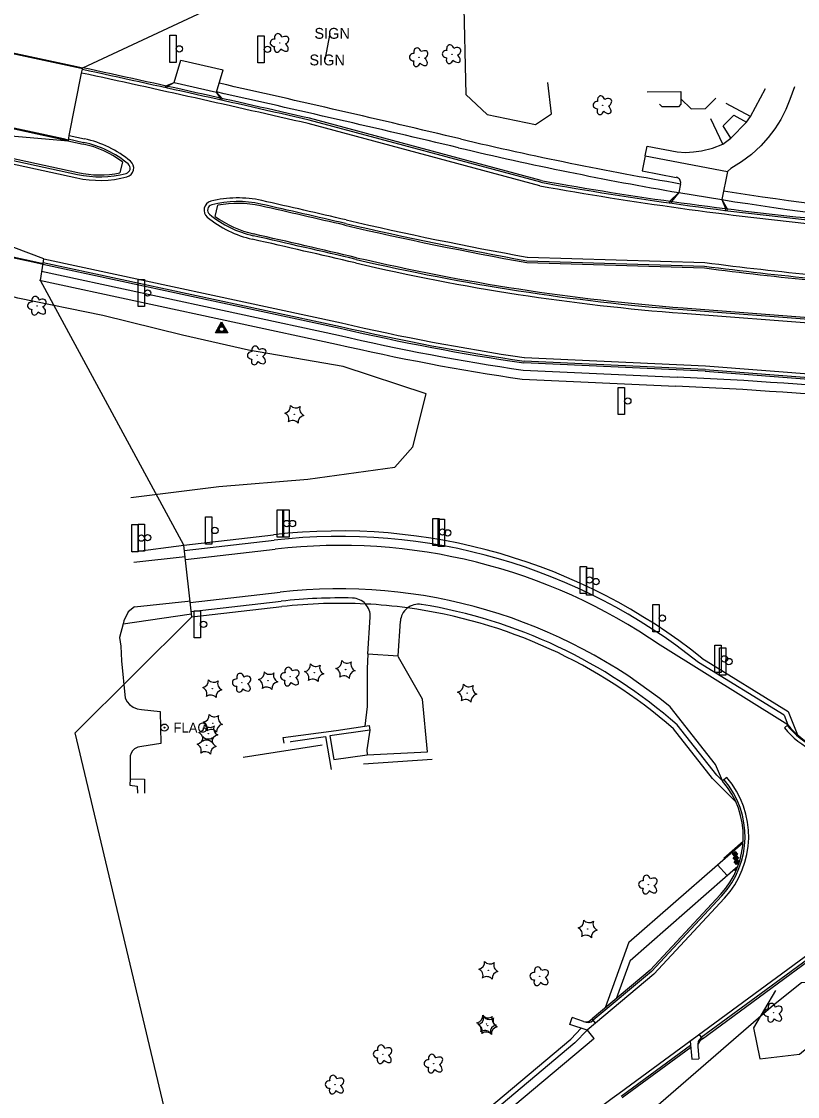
# Model space of a CAD drawing. Extents: x 588843 to 2552415, y 180129 to 269402.
# Drawn here: x 589955 to 590383, y 186401 to 186995 of the extents above; entities that cross this region are included whole.
import ezdxf

# ---------------------------------------------------------------- set-up
doc = ezdxf.new("R2010")
doc.units = 0
for name, color, linetype in [('Default', 7, 'Continuous'), ('E_BLD', 7, 'Continuous'), ('E_BLD_HvyDash', 7, 'Continuous'), ('E_FEN_ChainLink', 7, 'Continuous'), ('E_LAND_TreeLine', 7, 'Continuous'), ('E_LAND_Vegetation', 7, 'Continuous'), ('E_MISCPROP', 7, 'Continuous'), ('E_RDWY', 7, 'Continuous'), ('E_RDWY_AsphConc', 7, 'Continuous'), ('E_RDWY_C_and_G', 7, 'Continuous'), ('E_RDWY_Gravel', 7, 'Continuous'), ('E_SGN', 7, 'Continuous'), ('P_DWY', 7, 'Continuous'), ('P_MARK', 7, 'Continuous'), ('P_PATH_Sidewalk', 7, 'Continuous'), ('P_RDWY_C_and_G_30', 7, 'Continuous'), ('P_RDWY_C_and_GBack', 7, 'Continuous'), ('P_RDWY_C_and_GFace', 7, 'Continuous'), ('P_RDWY_LaneEdge', 7, 'Continuous'), ('P_RDWY_ShldAgg', 7, 'Continuous'), ('P_RDWY_ShldPaved', 7, 'Continuous')]:
    doc.layers.add(name, color=color, linetype=linetype)

# ---------------------------------------------------------------- blocks, each defined once
blk = doc.blocks.new('BSGN')
at = {"layer": 'E_SGN'}
blk.add_text('SIGN', height=12, dxfattribs=at).set_placement((-17.1, -6))
blk = doc.blocks.new('CTRE_2')
at = {"layer": 'E_LAND_Vegetation'}
blk.add_circle((0, 0), 0.223, dxfattribs=at)
for centre, start, end in [((-12, 9), 280.2067, 5.9716), ((-13.8, -5.9), 340.2113, 65.9762), ((1.8, 14.9), 220.2113, 305.9762), ((13.8, 5.9), 160.2113, 245.9762), ((-1.8, -14.9), 40.2113, 125.9762), ((12, -9), 100.2511, 185.9272)]:
    blk.add_arc(centre, 7.87, start, end, dxfattribs=at)
blk = doc.blocks.new('DTRE_2')
at = {"layer": 'E_LAND_Vegetation'}
blk.add_circle((-0.2, 0), 0.183, dxfattribs=at)
for centre, major_axis, ratio in [((-5.9, 0.2), (4.93, -0.12), 0.832022), ((-1.9, 5.3), (1.36, -4.98), 0.782863), ((4.1, 2.7), (-5.27, -2.93), 0.691916), ((-2.5, -5.2), (1.8, 4.86), 0.716896), ((3.5, -3.7), (-5.01, 4.58), 0.560249)]:
    blk.add_ellipse(centre, major_axis=major_axis, ratio=ratio, start_param=1.570796, end_param=4.712389, dxfattribs=at)
blk = doc.blocks.new('FPOL_1')
at = {"layer": 'E_MISCPROP'}
for radius in [4, 0.5]:
    blk.add_circle((0, 0), radius, dxfattribs=at)
blk.add_text('FLAG', height=10.8, dxfattribs=at).set_placement((10, -5.4))
blk = doc.blocks.new('SGN')
at = {"layer": 'E_SGN'}
blk.add_lwpolyline([(-3.5, -15), (-10.5, -15), (-10.5, 15), (-3.5, 15)], close=True, dxfattribs=at)
blk.add_circle((0, 0), 3.5, dxfattribs=at)
blk = doc.blocks.new('CP')
at = {"layer": 'P_MARK'}
for points in [[(-6.9, -4), (0, 7.9), (7, -4)], [(-6.4, -3.7), (0, 7.4), (6.5, -3.7)], [(-5.8, -3.4), (0, 6.6), (5.9, -3.4)], [(-5.3, -3), (0, 6.1), (5.4, -3)], [(-4.8, -2.7), (0, 5.5), (4.8, -2.7)]]:
    blk.add_lwpolyline(points, close=True, dxfattribs=at)
for radius in [4, 3.68, 3.36, 3.04, 2.72]:
    blk.add_circle((0, 0), radius, dxfattribs=at)
blk = doc.blocks.new('RAMPD_1')
at = {"layer": 'P_PATH_Sidewalk'}
for p, q in [((-0.01, 0), (-0.01, 0.02)), ((-0.01, 0.02), (0.01, 0.02)), ((0.01, 0), (-0.01, 0)), ((0.01, 0.02), (0.01, 0))]:
    blk.add_line(p, q, dxfattribs=at)
for centre in [(-0.0075, 0.0175), (-0.0075, 0.0137), (-0.0075, 0.01), (-0.0075, 0.0062), (-0.0075, 0.0025), (-0.0037, 0.0175), (-0.0037, 0.0137), (-0.0037, 0.01), (-0.0037, 0.0062), (-0.0037, 0.0025), (0, 0.0175), (0, 0.0137), (0, 0.01), (0, 0.0062), (0, 0.0025), (0.0038, 0.0175), (0.0038, 0.0137), (0.0038, 0.01), (0.0038, 0.0062), (0.0038, 0.0025), (0.0075, 0.0175), (0.0075, 0.0137), (0.0075, 0.01), (0.0075, 0.0062), (0.0075, 0.0025)]:
    blk.add_circle(centre, 0.00125, dxfattribs=at)

msp = doc.modelspace()

# ---------------------------------------------------------------- linework, layer by layer
at = {"layer": 'Default'}
msp.add_lwpolyline([(591615.09, 187246.23), (591637.48, 187198.53), (591342.5, 186657.05), (591340.04, 186646.33), (591325.15, 186588.94), (591314.68, 186544.52), (590335.16, 185755.94), (590089.6, 186237.3), (590063.71, 186267.8), (589984.27, 186602.34), (590048.74, 186666.43), (590044.21, 186706.17), (589965.01, 186852.44), (589966.96, 186864.3), (589738.46, 186950.56), (589980.48, 186929.54), (589980.82, 186932.54), (589987.79, 186967.01), (589988.43, 186969.95), (590832.85, 187364.29), (591607.16, 187360.88), (591615.35, 187246.35)], dxfattribs=at)
at = {"layer": 'E_BLD'}
for points in [[(590300.25, 186956.61), (590318.81, 186956.81), (590318.9, 186952.8), (590324.51, 186947.23), (590332.55, 186947.4), (590338.16, 186953.05)], [(590076.99, 186588.95), (590120.62, 186595.7)], [(590143.46, 186585.34), (590181.53, 186587.91)]]:
    msp.add_lwpolyline(points, dxfattribs=at)
at = {"layer": 'E_BLD_HvyDash'}
msp.add_lwpolyline([(590318.85, 186952.68), (590318.92, 186949.83), (590317.51, 186948.4), (590308.49, 186948.3), (590307.01, 186949.78)], dxfattribs=at)
at = {"layer": 'E_FEN_ChainLink'}
msp.add_lwpolyline([(590426, 186465.4), (590385.5, 186464.29), (590370.05, 186451.96), (590197.13, 186302.03)], dxfattribs=at)
at = {"layer": 'E_LAND_TreeLine'}
for points in [[(590198.79, 187010.99), (590200.11, 186955.11), (590211.92, 186944.17), (590238.52, 186938.56), (590247.38, 186944.52), (590245.46, 186961.73)], [(590014.98, 186732.45), (590063.58, 186738.57), (590112.84, 186742.66), (590160.88, 186749.13), (590170.83, 186760.5), (590178.14, 186789.72), (590132.33, 186804.85), (590080.03, 186813.95), (590043.49, 186822.21), (589999.48, 186833.03), (589952.51, 186842.61), (589914.19, 186853.29), (589898.07, 186840.93)], [(590371.19, 186459.99), (590358.95, 186439.39), (590362.44, 186422.21), (590384.44, 186424.88), (590398.24, 186436.31), (590418.8, 186438.08)]]:
    msp.add_lwpolyline(points, dxfattribs=at)
at = {"layer": 'E_RDWY'}
for points in [[(589925.47, 186982.93), (589984.99, 186970.24), (589988.34, 186969.51)], [(590299.17, 186921.3), (590300.23, 186926.54), (590316.88, 186923.38), (590321.39, 186923.18), (590325.9, 186923.4), (590330.36, 186924.03), (590330.36, 186924.03), (590336.33, 186925.54), (590342.06, 186927.79), (590342.06, 186927.79), (590346.51, 186930.96), (590355.11, 186939.82), (590357.35, 186942.9), (590365.71, 186958.46)], [(590381.75, 186959.33), (590379.15, 186952.43), (590376.87, 186946.78), (590374.11, 186941.35), (590370.88, 186936.19), (590367.21, 186931.32), (590363.13, 186926.8), (590363.13, 186926.8), (590357.99, 186922.08), (590352.41, 186917.9), (590346.43, 186914.31), (590346.43, 186914.31), (590344.6, 186912.65)], [(589980.53, 186929.97), (589977.73, 186930.63), (589977.73, 186930.63), (589918.47, 186943.34)], [(589905.38, 186874.97), (589960.82, 186863.13), (589966.55, 186861.85)], [(590044.94, 186699.75), (590016.56, 186696.56)], [(590017.06, 186672.04), (590046.47, 186675.17), (590047.73, 186675.31)], [(590017.06, 186672.04), (590013.51, 186669.32), (590011.2, 186664.29), (590010.74, 186662.65), (590008.68, 186655.08), (590009.49, 186650.29), (590009.89, 186642.25), (590011.8, 186621.54), (590012.87, 186619.63), (590014.33, 186617.99), (590014.33, 186617.99), (590016.31, 186616.59), (590018.56, 186615.7), (590020.96, 186615.36), (590020.96, 186615.36), (590031.21, 186614.3), (590031.56, 186596.6), (590021.04, 186594.87), (590018.88, 186594.55), (590016.97, 186593.51), (590016.97, 186593.51), (590015.89, 186592.42), (590015.12, 186591.1), (590014.69, 186589.63), (590014.69, 186589.63), (590014.52, 186576.93), (590014.41, 186573.48)]]:
    msp.add_lwpolyline(points, dxfattribs=at)
at = {"layer": 'E_RDWY_AsphConc'}
for points in [[(590357.35, 186942.9), (590343.99, 186950.11)], [(590342.06, 186927.79), (590335.41, 186941.69)], [(590346.51, 186930.96), (590342.2, 186937.74), (590348.08, 186943.81), (590355.11, 186939.82)], [(590099.7, 186596.68), (590099.08, 186599.82), (590128.38, 186603.74), (590144.28, 186606.18), (590146.74, 186606.53), (590147.01, 186603.96), (590124.97, 186600.77), (590127.2, 186587.71), (590145.48, 186590.33), (590178.97, 186591.9)], [(590103.38, 186597.22), (590103.34, 186597.67), (590122.52, 186600.38), (590125.72, 186582.18)], [(590014.41, 186573.48), (590018.53, 186572.92), (590018.6, 186569.13)], [(590014.52, 186576.93), (590022.5, 186576.83), (590022.48, 186569.14)]]:
    msp.add_lwpolyline(points, dxfattribs=at)
at = {"layer": 'E_RDWY_C_and_G'}
for points in [[(589925.72, 186983.38), (589985.18, 186970.66), (589988.43, 186969.95)], [(589979.81, 186929.6), (589977.55, 186930.13), (589977.55, 186930.13), (589918.31, 186942.9)], [(589905.08, 186874.55), (589960.75, 186862.61), (589966.47, 186861.34)]]:
    msp.add_lwpolyline(points, dxfattribs=at)
at = {"layer": 'E_RDWY_Gravel'}
for points in [[(590044.24, 186705.93), (590016.09, 186702.24)], [(590010.74, 186662.65), (590047.13, 186667.96), (590048.54, 186668.14)], [(590145.98, 186646.07), (590145.47, 186637.79), (590145.56, 186616.98), (590144.28, 186606.18), (590146.74, 186606.53), (590147.01, 186603.96), (590145.43, 186593.05), (590145.48, 186590.33), (590178.97, 186591.9), (590176.11, 186620.94), (590162.9, 186644.26), (590162.75, 186645.05)]]:
    msp.add_lwpolyline(points, dxfattribs=at)
at = {"layer": 'E_SGN'}
msp.add_lwpolyline([(590124.97, 186988.93), (590122.21, 186974.23)], dxfattribs=at)
at = {"layer": 'P_DWY'}
for points in [[(590038.98, 186961.74), (590042.6, 186974.03)], [(590042.6, 186974.03), (590065.97, 186968.77)], [(590062.36, 186956.52), (590065.97, 186968.77)], [(590033.98, 186958.93), (590034.26, 186959.89), (590038.98, 186961.74)], [(590034.95, 186958.71), (590035.24, 186959.67), (590038.98, 186961.74)], [(590038.98, 186961.74), (590062.36, 186956.52)], [(590064.21, 186952.18), (590064.49, 186953.13), (590062.36, 186956.52)], [(590065.19, 186951.96), (590065.47, 186952.93), (590062.36, 186956.52)], [(590299.17, 186921.3), (590297.5, 186912.96)], [(590299.17, 186921.3), (590344.6, 186912.65)], [(590297.5, 186912.96), (590316.36, 186909.37)], [(590344.6, 186912.65), (590341.46, 186897.05)], [(590318.75, 186905.84), (590317.76, 186900.95)], [(590317.76, 186900.95), (590312.73, 186896.21), (590312.53, 186895.23)], [(590317.76, 186900.95), (590313.72, 186896.07), (590313.52, 186895.09)], [(590317.76, 186900.95), (590341.46, 186897.05)], [(590341.46, 186897.05), (590343.52, 186892.1), (590343.33, 186891.12)], [(590341.46, 186897.05), (590344.52, 186891.97), (590344.32, 186890.99)], [(590145.98, 186646.07), (590147.22, 186666.27)], [(590162.75, 186645.05), (590163.91, 186664.09)], [(590145.98, 186646.07), (590162.75, 186645.05)]]:
    msp.add_lwpolyline(points, dxfattribs=at)
for centre, radius, start, end in [((590315.8, 186906.43), 3, 348.6361, 79.22961), ((590137.24, 186666.88), 10, 356.49387, 88.56059), ((590130.38, 186393.97), 280, 82.30834, 87.0806), ((590173.89, 186663.48), 10, 80.82835, 176.49387)]:
    msp.add_arc(centre, radius, start, end, dxfattribs=at)
at = {"layer": 'P_PATH_Sidewalk'}
for p, q in [((590290.2, 186486.77), (590339.17, 186529.54)), ((590290.79, 186476.66), (590343.36, 186522.58)), ((590290.2, 186486.77), (590276.99, 186450.39)), ((590290.79, 186476.66), (590283.12, 186455.53))]:
    msp.add_line(p, q, dxfattribs=at)
for points in [[(589965.53, 186857.45), (590129.77, 186822.13)], [(589964.53, 186852.55), (590128.64, 186817.26)], [(590231.75, 186802.83), (590316.86, 186798.97)], [(590231.27, 186797.85), (590316.1, 186794)], [(590339.17, 186529.54), (590353.26, 186541.84)], [(590344.49, 186523.57), (590339.17, 186529.54)], [(590343.36, 186522.58), (590350.42, 186528.75)]]:
    msp.add_lwpolyline(points, dxfattribs=at)
for centre, radius, start, end in [((587538.6, 175698.46), 11542.48, 76.683887, 77.363031), ((587538.6, 175698.46), 11537.48, 76.683887, 77.364673), ((590648.53, 188837.91), 1960, 256.68389, 260.31348), ((590648.53, 188837.91), 1965, 256.68389, 260.30921), ((590648.53, 188837.91), 1960, 261.01551, 264.41332), ((590648.53, 188837.91), 1965, 261.00945, 264.41332), ((590411.31, 188030.77), 1241, 256.88722, 261.68035), ((590411.31, 188030.77), 1246, 256.88722, 261.69179), ((590202.77, 184296.57), 2505, 84.68703, 87.38941), ((590202.77, 184296.57), 2500, 84.68703, 87.40174)]:
    msp.add_arc(centre, radius, start, end, dxfattribs=at)
at = {"layer": 'P_RDWY_C_and_G_30'}
for p, q in [((590010.33, 186917.96), (590008.96, 186911.79)), ((590332.25, 186802.22), (590402.19, 186796.88))]:
    msp.add_line(p, q, dxfattribs=at)
for points in [[(589887.78, 186933.01), (589915.39, 186927.24), (589985.72, 186911.99)], [(589980.17, 186929.61), (589988.68, 186927.72)], [(589966.32, 186861.37), (590130.68, 186826.02)], [(590332.25, 186802.22), (590232.13, 186806.82)]]:
    msp.add_lwpolyline(points, dxfattribs=at)
for centre, radius, start, end in [((589976.59, 186872.02), 57, 53.70371, 77.73492), ((589997.83, 186967.69), 57, 257.73285, 281.25309), ((590411.31, 188030.77), 1237, 256.88722, 261.67115), ((590414.63, 186637.03), 47.5, 219.57139, 314.87409)]:
    msp.add_arc(centre, radius, start, end, dxfattribs=at)
at = {"layer": 'P_RDWY_C_and_GBack'}
for p, q in [((590061.66, 186887.75), (590063.04, 186893.93)), ((590320.12, 186837.25), (590405.51, 186830.72)), ((590378.02, 186606.77), (590376.11, 186605.14)), ((590301.88, 186471.3), (590269.81, 186444.35))]:
    msp.add_line(p, q, dxfattribs=at)
for points in [[(590241.68, 186907.59), (590113.72, 186941.98)], [(590233.75, 186862.28), (590331.88, 186859.31)], [(590342.6, 186533.2), (590353.3, 186542.55)], [(590342.6, 186533.2), (590342.94, 186532.83)], [(590348.26, 186526.86), (590348.59, 186526.48)], [(590348.59, 186526.48), (590350.04, 186527.75)], [(590301.88, 186471.3), (590340.78, 186513.12)], [(590430.9, 186506.84), (590330.77, 186433.23)], [(590257.54, 186441.26), (590258.81, 186445.06)], [(590265.16, 186442.94), (590258.81, 186445.06)], [(590271.74, 186442.06), (590267.03, 186438.1)], [(590271.74, 186442.06), (590269.81, 186444.36)], [(590267.03, 186438.09), (590257.54, 186441.26)], [(590328.99, 186435.64), (590330.77, 186433.23)], [(590324.03, 186431.99), (590324.89, 186422.03)], [(590324.33, 186428.49), (590286.48, 186400.67)], [(590328.3, 186429.03), (590328.87, 186422.37)], [(590324.89, 186422.03), (590328.87, 186422.37)]]:
    msp.add_lwpolyline(points, dxfattribs=at)
for centre, radius, start, end in [((587538.83, 175699.6), 11533.48, 77.099821, 77.737519), ((590588.67, 188845.78), 1969, 259.84977, 264.41332), ((590074.08, 186838.01), 57, 77.28139, 101.17232), ((588258.51, 178813.68), 8284.16, 76.920049, 77.251237), ((590095.46, 186933.65), 57, 233.62307, 257.13615), ((590588.67, 188845.78), 2015, 256.93886, 259.85481), ((588075.53, 178014.85), 9087.67, 76.870938, 77.239565), ((590411.31, 188030.77), 1197, 256.88722, 265.63074), ((590588.67, 188845.78), 2003, 262.63415, 264.41332), ((590306.37, 186545.13), 47, 317.06994, 40.74025), ((590266.42, 186446.73), 4, 251.5218, 310.12475), ((588992.34, 187958.43), 1981, 310.12475, 310.15545), ((591502.63, 184836.01), 1984, 126.26743, 126.44519), ((590332.29, 186429.37), 4, 126.29779, 184.90073), ((591502.63, 184836.01), 1981, 126.26708, 126.29779)]:
    msp.add_arc(centre, radius, start, end, dxfattribs=at)
at = {"layer": 'P_RDWY_C_and_GFace'}
for p, q in [((590320.05, 186836.25), (590466.43, 186825.07)), ((590332.31, 186803.22), (590422.03, 186796.37)), ((590302.57, 186470.57), (590270.46, 186443.59))]:
    msp.add_line(p, q, dxfattribs=at)
for points in [[(590241.46, 186906.62), (590113.47, 186941.01)], [(589887.62, 186932.02), (589915.18, 186926.26), (589985.51, 186911.01)], [(589980.38, 186930.59), (589988.9, 186928.7)], [(589966.53, 186862.35), (590130.9, 186827)], [(590233.85, 186863.28), (590331.96, 186860.3)], [(590332.31, 186803.22), (590232.23, 186807.81)], [(590302.57, 186470.57), (590341.52, 186512.44)], [(590430.31, 186507.64), (590330.18, 186434.03)], [(590324.23, 186429.66), (590285.89, 186401.47)]]:
    msp.add_lwpolyline(points, dxfattribs=at)
for centre, radius, start, end in [((587538.83, 175699.6), 11532.48, 77.099914, 77.737519), ((589976.59, 186872.02), 58, 50.46722, 77.73492), ((589997.83, 186967.69), 58, 257.73285, 284.48959), ((590011.59, 186914.44), 3, 284.48959, 50.46722), ((590588.67, 188845.78), 1970, 259.84853, 264.41332), ((590060.4, 186891.28), 3, 104.4088, 230.38658), ((590074.08, 186838.01), 58, 77.28139, 104.4088), ((588258.51, 178813.68), 8285.16, 76.920049, 77.251237), ((590095.46, 186933.65), 58, 230.38658, 257.13615), ((590588.67, 188845.78), 2014, 256.93886, 259.85272), ((588075.53, 178014.85), 9086.67, 76.870938, 77.239565), ((590411.31, 188030.77), 1198, 256.88722, 265.63074), ((590588.67, 188845.78), 2002, 262.63275, 264.41332), ((590411.31, 188030.77), 1236, 256.88683, 261.66884), ((590414.63, 186637.03), 48, 219.57139, 314.87409), ((590306.37, 186545.13), 48, 317.06994, 40.74025), ((590267.33, 186447.15), 4.74, 242.77108, 311.27241), ((590332.91, 186430.15), 4.74, 125.15013, 193.65145)]:
    msp.add_arc(centre, radius, start, end, dxfattribs=at)
at = {"layer": 'P_RDWY_LaneEdge'}
for p, q in [((590319.89, 186834.26), (590466.28, 186823.07)), ((590232.4, 186809.81), (590332.41, 186805.22)), ((590332.41, 186805.22), (590422.05, 186798.37)), ((590045.09, 186698.22), (590094.76, 186703.93)), ((590047.83, 186674.38), (590097.5, 186680.09)), ((590378.02, 186606.77), (590307.48, 186650.83)), ((590337.93, 186584.95), (590312.9, 186616.75)), ((590341.98, 186575.81), (590337.93, 186584.95)), ((590344.26, 186577.77), (590341.98, 186575.81)), ((590429.12, 186509.26), (590284.71, 186403.08)), ((590303.95, 186469.12), (590271.74, 186442.05))]:
    msp.add_line(p, q, dxfattribs=at)
for points in [[(590241.02, 186904.66), (590112.99, 186939.07)], [(589887.3, 186930.04), (589914.76, 186924.31), (589985.08, 186909.06)], [(589980.82, 186932.54), (589989.33, 186930.65)], [(589966.96, 186864.3), (590131.33, 186828.95)], [(590234.06, 186865.27), (590332.12, 186862.3)], [(590303.95, 186469.12), (590342.98, 186511.08)], [(590267.03, 186438.09), (590270.85, 186433.54), (590270.55, 186433.22), (590165.49, 186344.93)]]:
    msp.add_lwpolyline(points, dxfattribs=at)
for centre, radius, start, end in [((587538.83, 175699.6), 11530.48, 77.1001, 77.737519), ((589976.59, 186872.02), 60, 50.46722, 77.73492), ((590011.59, 186914.44), 5, 284.48959, 50.46722), ((589997.83, 186967.69), 60, 257.73285, 284.48959), ((590588.67, 188845.78), 1972, 259.84604, 264.41332), ((590060.4, 186891.28), 5, 104.4088, 230.38658), ((590074.08, 186838.01), 60, 77.28139, 104.4088), ((588258.51, 178813.68), 8287.16, 76.920049, 77.251237), ((590095.46, 186933.65), 60, 230.38658, 257.13615), ((590588.67, 188845.78), 2012, 256.93886, 259.84854), ((588075.47, 178014.59), 9084.94, 76.870936, 77.239579), ((590411.31, 188030.77), 1200, 256.88722, 265.63074), ((590588.67, 188845.78), 2000, 262.62993, 264.41332), ((590411.31, 188030.77), 1234, 256.88604, 261.6633), ((590130.38, 186393.97), 312, 55.41468, 96.55539), ((590130.38, 186393.97), 288, 50.67262, 96.55539), ((590414.63, 186637.03), 50, 219.61552, 314.87409), ((590306.37, 186545.13), 50, 317.06994, 40.74025), ((590306.37, 186545.13), 50, 317.06994, 40.74025), ((591459.91, 184804.6), 1984, 126.32317, 130.60253)]:
    msp.add_arc(centre, radius, start, end, dxfattribs=at)
at = {"layer": 'P_RDWY_ShldAgg'}
for p, q in [((590044.17, 186706.17), (590093.85, 186711.88)), ((590048.74, 186666.43), (590098.41, 186672.14))]:
    msp.add_line(p, q, dxfattribs=at)
for points in [[(590330.43, 186643.73), (590378.19, 186614.28), (590383.31, 186601.32)], [(590349.39, 186564.07), (590336.44, 186577.13), (590314.74, 186604.71)], [(590160.34, 186351.05), (590258.09, 186433.19), (590263.88, 186439.14)]]:
    msp.add_lwpolyline(points, dxfattribs=at)
for radius, start, end in [(320, 51.30636, 96.55539), (280, 87.0806, 96.55539), (280, 48.81954, 82.30834)]:
    msp.add_arc((590130.38, 186393.97), radius, start, end, dxfattribs=at)
at = {"layer": 'P_RDWY_ShldPaved'}
for p, q in [((590044.52, 186703.19), (590094.19, 186708.9)), ((590048.4, 186669.41), (590098.07, 186675.12)), ((590375.88, 186612.17), (590328.7, 186641.27)), ((590338.7, 186579.12), (590316.93, 186606.78)), ((590341.98, 186575.81), (590338.7, 186579.12)), ((590260.37, 186431.19), (590267.03, 186438.1)), ((590260.37, 186431.19), (590162.27, 186348.75))]:
    msp.add_line(p, q, dxfattribs=at)
msp.add_lwpolyline([(590375.88, 186612.17), (590378.02, 186606.77)], dxfattribs=at)
for radius, start, end in [(317, 51.27314, 96.55539), (283, 88.54796, 96.55539), (283, 48.76298, 80.82835)]:
    msp.add_arc((590130.38, 186393.97), radius, start, end, dxfattribs=at)

# ---------------------------------------------------------------- block references
at = {"layer": 'E_LAND_Vegetation', "xscale": 0.5, "yscale": 0.5}
for name, p in [('DTRE_2', (590097.39, 186983.59)), ('DTRE_2', (590192.47, 186977.38)), ('DTRE_2', (590174.29, 186975.68)), ('DTRE_2', (590275.8, 186949.18)), ('DTRE_2', (589963.31, 186838.36)), ('DTRE_2', (590084.82, 186810.93)), ('CTRE_2', (590105.29, 186778.46)), ('DTRE_2', (590103.09, 186633.46)), ('CTRE_2', (590116.31, 186635.61)), ('CTRE_2', (590133.61, 186637.4)), ('CTRE_2', (590059.98, 186626.82)), ('DTRE_2', (590076.48, 186630.07)), ('CTRE_2', (590090.83, 186631.23)), ('CTRE_2', (590200.84, 186624.34)), ('CTRE_2', (590060.29, 186607.73)), ('CTRE_2', (590057.76, 186601.92)), ('CTRE_2', (590056.89, 186595.5)), ('DTRE_2', (590300.98, 186518.5)), ('CTRE_2', (590267.37, 186494.06)), ('CTRE_2', (590212.53, 186471.23)), ('DTRE_2', (590240.94, 186467.84)), ('DTRE_2', (590370.08, 186447.71)), ('CTRE_2', (590211.49, 186441.48)), ('CTRE_2', (590212.13, 186440.58)), ('DTRE_2', (590154.33, 186424.77)), ('DTRE_2', (590182.43, 186419.61)), ('DTRE_2', (590127.83, 186407.99))]:
    msp.add_blockref(name, p, dxfattribs=at)
at = {"layer": 'E_MISCPROP', "xscale": 0.5, "yscale": 0.5}
msp.add_blockref('FPOL_1', (590033.53, 186605.3), dxfattribs=at)
at = {"layer": 'E_SGN', "xscale": 0.5, "yscale": 0.5}
for name, p in [('BSGN', (590124.97, 186988.93)), ('SGN', (590041.75, 186980.35)), ('SGN', (590090.46, 186980.1)), ('BSGN', (590122.21, 186974.23)), ('SGN', (590024.27, 186845.5)), ('SGN', (590289.58, 186785.74)), ('SGN', (590061.41, 186714.25)), ('SGN', (590101.08, 186718.08)), ('SGN', (590104.3, 186718.07)), ('SGN', (590187.1, 186713.44)), ('SGN', (590020.8, 186710.02)), ('SGN', (590024.24, 186710.3)), ('SGN', (590190.04, 186712.9)), ('SGN', (590268.44, 186686.86)), ('SGN', (590272, 186686)), ('SGN', (590308.63, 186665.81)), ('SGN', (590055.16, 186662.4)), ('SGN', (590342.95, 186643.29)), ('SGN', (590345.41, 186641.81))]:
    msp.add_blockref(name, p, dxfattribs=at)
at = {"layer": 'P_MARK', "xscale": 0.5, "yscale": 0.5}
msp.add_blockref('CP', (590065.16, 186825.49), dxfattribs=at)
at = {"layer": 'P_PATH_Sidewalk', "xscale": 100.00000000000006, "yscale": 100.00000000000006, "rotation": 39.38248620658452}
for p in [(590349.42, 186534.68), (590349.91, 186532.5), (590350.41, 186530.32)]:
    msp.add_blockref('RAMPD_1', p, dxfattribs=at)

doc.saveas('drawing.dxf')
